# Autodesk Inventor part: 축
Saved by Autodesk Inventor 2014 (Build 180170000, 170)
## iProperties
Created: 2026-08
Part Number: 축
Material: 일반
Document SubType Name: Modeling
Designer: dg
Density: 1 g/cm^3
Appearance: 기본값
Author: dg
Author: jhkim
Creation Date: 2026-07-31
Sending System: Autodesk Inventor 2027
Preprocessor: ST-DEVELOPER v20.1
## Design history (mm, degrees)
node "축1"
node "솔리드1"
node "기준1"
